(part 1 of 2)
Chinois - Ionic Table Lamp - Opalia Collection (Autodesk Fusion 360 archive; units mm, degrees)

design "Marble Base - Ionic Table Lamp - Ketra Ready - 120V - Opalia Collection" references "Ketra - A20 Tunable Lamp", "Facet Petite", "Arca Tall", "Chinois", "Arca Petite", "Trove - TL", "Marble Base - Ionic Table Lamp - Ketra Ready - 120V"
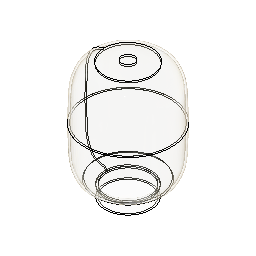
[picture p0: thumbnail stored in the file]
component_insert "Component Insert2"
component_insert "Component Insert3"
component_insert "Component Insert4"
component_insert "Component Insert5"
position "Position1"
component_insert "Component Insert6"
component_insert "Component Insert7"
component_insert "Component Insert8"

design "Arca Petite"
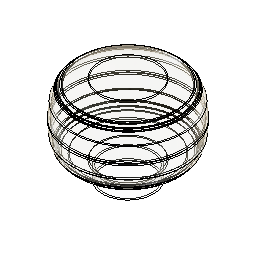
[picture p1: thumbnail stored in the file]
sketch "Sketch1" plane through (0, 0, 0) normal (0, 1, 0) x axis (1, 0, 0)
  line L1 (0, 101.6) -> (0, -101.6)
  line L2 (127, 0) -> (-127, 0)
  line L3 (63.5, 101.6) -> (-63.5, 101.6)
  perpendicular L1 L2
  parallel L2 L3
sketch "Sketch2" plane through (0, 0, 0) normal (0, 1, 0) x axis (1, 0, 0)
  line L1 (0, 101.6) -> (0, -101.6)
  line L2 (0, -76.2) -> (0, 101.6)
  line L3 (127, 0) -> (-127, 0)
  line L4 (114.3, 0) -> (-114.3, 0)
  line L5 (50.8, 101.6) -> (50.8, 63.5)
  line L6 (-50.8, 101.6) -> (50.8, 101.6)
  line L7 (-50.8, 63.5) -> (-50.8, 101.6)
  line L8 (63.5, 101.6) -> (-63.5, 101.6)
  line L9 (114.3, -76.2) -> (114.3, 63.5)
  line L10 (-114.3, -76.2) -> (114.3, -76.2)
  line L11 (-114.3, 63.5) -> (-114.3, -76.2)
  line L12 (-50.8, 63.5) -> (-114.3, 63.5)
  line L13 (114.3, 63.5) -> (50.8, 63.5)
  point P2 (0, 101.6)
  point P5 (0, 101.6)
  point P6 (0, -76.2)
  point P9 (-114.3, 0)
  point P10 (114.3, 0)
  point P11 (50.8, 101.6)
  point P19 (50.8, 63.5)
  coincident P2 P5
  coincident L1 P6
  coincident L3 P9
  coincident L3 P10
  vertical L5
  horizontal L6
  vertical L7
  coincident P11 L8
  horizontal L12
  vertical L9
  horizontal L10
  vertical L11
  coincident P19 L12
  collinear L12 L13
derived_base_feature "Derived Base Feature"
revolve "Revolve1" sketch "Sketch4" AlongAngle 360 bodies "Arca Petite"
shell "Shell1" innerThickness 3.81
component_from_bodies "Body->Comp"
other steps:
base_feature "Base Feature" bodies "Arca Petite"
create_component "CreateComponent1"
remove_body "RemoveBody1"
named bodies: "Arca Petite"

design "Neoprene Pad"
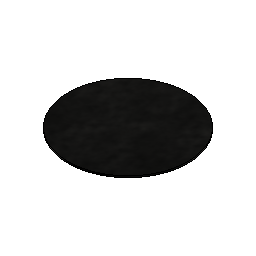
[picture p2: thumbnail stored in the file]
sketch "Sketch1" plane through (0, 0, 0) normal (0, 0, 1) x axis (1, 0, 0)
  circle C1 centre (0, 0) radius 57.15
  point P1 (0, 0)
  point P2 (0, 0)
  coincident P1 P2
extrude "Extrude1" new body sketch "Sketch1" along normal blind 1.5875 bodies "Neoprene Pad"
component_from_bodies "Body->Comp"
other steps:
base_feature "Base Feature" bodies "Neoprene Pad"
create_component "CreateComponent1"
remove_body "RemoveBody1"
named bodies: "Neoprene Pad"

design "T9 - Bulb"
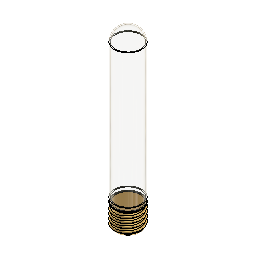
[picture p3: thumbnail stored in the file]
sketch "Sketch1" plane through (0, 0, 0) normal (0, 1, 0) x axis (1, 0, 0)
  line L1 (0, -166.37) -> (0, 0)
  line L2 (13.97, -13.97) -> (13.97, -152.4)
  line L3 (-13.97, -152.4) -> (-13.97, -13.97)
  line L4 (0, 0) -> (0, -166.37)
  line L5 (12.97, -13.97) -> (12.97, -152.4)
  line L6 (-12.97, -152.4) -> (-12.97, -13.97)
  line L7 (-12.3978, -10.16) -> (-13.4404, -10.16)
  line L8 (13.4404, -10.16) -> (12.3978, -10.16)
  arc A1 centre (0, -152.4) radius 13.97 clockwise from (13.97, -152.4) to (-13.97, -152.4)
  arc A2 centre (0, -152.4) radius 12.97 clockwise from (12.97, -152.4) to (-12.97, -152.4)
  arc A3 centre (0, -13.97) radius 13.97 clockwise from (13.4404, -10.16) to (13.97, -13.97)
  arc A4 centre (0, -13.97) radius 13.97 clockwise from (-13.97, -13.97) to (-13.4404, -10.16)
  arc A5 centre (0, -13.97) radius 12.97 clockwise from (12.3978, -10.16) to (12.97, -13.97)
  arc A6 centre (0, -13.97) radius 12.97 clockwise from (-12.97, -13.97) to (-12.3978, -10.16)
  point P1 (0, 0)
  point P2 (0, 0)
  point P3 (0, -166.37)
  point P10 (0, 0)
  point P17 (13.4404, -10.16)
  point P19 (12.3978, -10.16)
  point P4 (13.97, -152.4)
  point P5 (13.97, -13.97)
  coincident P1 P2
  vertical L1
  tangent L2 A3
  tangent L3 A3
  parallel L2 L3
  tangent L3 A1
  tangent L2 A1
  midpoint P3 A1
  coincident P1 P10
  perpendicular L1 L7
  coincident P17 L7
  concentric A3 A4
  coincident P10 A3
  concentric A1 A2
  tangent L5 A2
  tangent L5 A5
  tangent L6 A5
  tangent L6 A2
  coincident P19 L7
  concentric A5 A6
  collinear L7 L8
  dimension "d6" distance L2 L3 = 27.94
  dimension "d7" distance P4 P5 = 138.43
revolve "Revolve1" sketch "Sketch1" AlongAngle 360 bodies "T9"
derived_base_feature "Derived Base Feature" bodies "E26 Base"
align "Align1"
move "Move1"
component_from_bodies "Body->Comp1"
component_from_bodies "Body->Comp2"
copy_paste "CutPaste1"
copy_paste "CutPaste2"
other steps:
base_feature "Base Feature1" bodies "T9"
base_feature "Base Feature1" bodies "E26 Base"
create_component "CreateComponent1"
create_component "CreateComponent2"
remove_body "RemoveBody1"
create_component "CreateComponent3"
remove_body "RemoveBody2"
remove_instance "RemoveInstance1"
remove_instance "RemoveInstance2"
named bodies: "T9", "E26 Base"

design "Marble Base - Silicone Gasket"
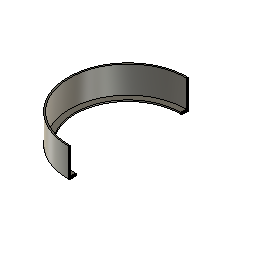
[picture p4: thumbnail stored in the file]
sketch "Sketch1" plane through (0, 0, 0) normal (0, 0, 1) x axis (1, 0, 0)
  circle C1 centre (0, 0) radius 53.34
  point P1 (0, 0)
  point P2 (0, 0)
  coincident P1 P2
extrude "Extrude1" new body sketch "Sketch1" along normal blind 25.4 bodies "Silicone Gasket"
shell "Shell1" innerThickness 1.27
sketch "Sketch2" plane through (0, 0, 1.27) normal (0, 0, 1) x axis (-1, 0, 0)
  circle C1 centre (0, 0) radius 52.07
  circle C2 centre (0, 0) radius 46.99
  concentric C1 C2
extrude "Extrude2" cut sketch "Sketch2" profile of C2 against normal blind 12.7
component_from_bodies "Body->Comp"
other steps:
base_feature "Base Feature" bodies "Silicone Gasket"
create_component "CreateComponent1"
remove_body "RemoveBody1"
named bodies: "Silicone Gasket"

design "2-Pole Plug End"
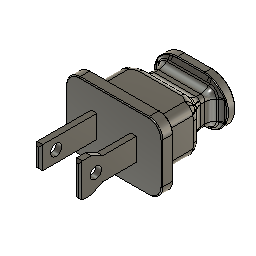
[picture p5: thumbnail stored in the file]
sketch "Sketch1" plane through (0, 0, 0) normal (0, 1, 0) x axis (1, 0, 0)
  line L1 (9.6837, 9.525) -> (-9.6837, 9.525)
  line L2 (13.4938, -5.715) -> (13.4938, 5.715)
  line L3 (-9.6837, -9.525) -> (9.6837, -9.525)
  line L4 (-13.4937, 5.715) -> (-13.4937, -5.715)
  line L5 (13.4938, -9.525) -> (-13.4937, 9.525)
  line L6 (-13.4937, -9.525) -> (13.4938, 9.525)
  arc A1 centre (-9.6837, -5.715) radius 3.81 clockwise from (-9.6837, -9.525) to (-13.4937, -5.715)
  arc A2 centre (9.6837, -5.715) radius 3.81 clockwise from (13.4938, -5.715) to (9.6837, -9.525)
  arc A3 centre (9.6837, 5.715) radius 3.81 clockwise from (9.6837, 9.525) to (13.4938, 5.715)
  arc A4 centre (-9.6837, 5.715) radius 3.81 clockwise from (-13.4937, 5.715) to (-9.6837, 9.525)
  point P6 (0, 0)
  point P1 (0, 0)
  point P5 (-13.4937, -9.525)
  point P4 (13.4938, -9.525)
  point P3 (13.4938, 9.525)
  point P2 (-13.4937, 9.525)
  horizontal L1
  perpendicular L1 L2
  parallel L1 L3
  parallel L2 L4
  coincident L5 P6
  coincident L6 P6
  coincident P1 P6
  coincident P5 L4
  coincident P5 L3
  tangent L4 A1
  tangent L3 A1
  coincident P4 L3
  coincident P4 L2
  tangent L3 A2
  tangent L2 A2
  equal A1 A2
  coincident P3 L2
  coincident P3 L1
  tangent L2 A3
  tangent L1 A3
  equal A1 A3
  coincident P2 L1
  coincident P2 L4
  tangent L1 A4
  tangent L4 A4
  equal A1 A4
  dimension "d1" distance P4 P5 = 26.9875
  dimension "d2" distance P2 P5 = 19.05
  dimension "d3" radius A1 = 3.81
extrude "Extrude1" new body sketch "Sketch1" profile of L1 L2 L3 L4 A1 A2 A3 A4 along normal blind 3.175
sketch "Sketch2" plane through (0, 3.175, 0) normal (0, 1, 0) x axis (-1, 0, 0)
  line L1 (9.6837, -9.525) -> (-9.6837, -9.525)
  line L2 (13.4937, 5.715) -> (13.4937, -5.715)
  line L3 (-9.6837, 9.525) -> (9.6837, 9.525)
  line L4 (-13.4938, -5.715) -> (-13.4938, 5.715)
  line L5 (10.16, -6.35) -> (-10.16, -6.35)
  line L6 (10.16, 6.35) -> (10.16, -6.35)
  line L7 (-10.16, 6.35) -> (10.16, 6.35)
  line L8 (-10.16, -6.35) -> (-10.16, 6.35)
  line L9 (10.16, 6.35) -> (-10.16, -6.35)
  line L10 (-10.16, 6.35) -> (10.16, -6.35)
  arc A1 centre (-9.6837, -5.715) radius 3.81 clockwise from (-9.6837, -9.525) to (-13.4938, -5.715)
  arc A2 centre (9.6837, -5.715) radius 3.81 clockwise from (13.4937, -5.715) to (9.6837, -9.525)
  arc A3 centre (9.6837, 5.715) radius 3.81 clockwise from (9.6837, 9.525) to (13.4937, 5.715)
  arc A4 centre (-9.6837, 5.715) radius 3.81 clockwise from (-13.4938, 5.715) to (-9.6837, 9.525)
  point P18 (0, 0)
  point P1 (0, 0)
  horizontal L5
  perpendicular L5 L6
  parallel L5 L7
  parallel L6 L8
  coincident L9 P18
  coincident L10 P18
  coincident P1 P18
extrude "Extrude2" add sketch "Sketch2" profile of L5 L6 L7 L8 along normal blind 9.525
sketch "Sketch3" plane through (0, 12.7, 0) normal (0, 1, 0) x axis (-1, 0, 0)
  line L1 (-10.16, -6.35) -> (-10.16, 6.35)
  line L2 (10.16, -6.35) -> (-10.16, -6.35)
  line L3 (10.16, 6.35) -> (10.16, -6.35)
  line L4 (-10.16, 6.35) -> (10.16, 6.35)
  line L5 (-7.1437, 3.9688) -> (7.1437, 3.9688)
  line L6 (-7.1437, -3.9688) -> (-7.1437, 3.9688)
  line L7 (7.1437, -3.9688) -> (-7.1437, -3.9688)
  line L8 (7.1437, 3.9688) -> (7.1437, -3.9688)
  line L9 (-7.1437, -3.9688) -> (7.1437, 3.9688)
  line L10 (7.1437, -3.9688) -> (-7.1437, 3.9688)
  point P10 (0, 0)
  point P1 (0, 0)
  point P8 (-7.1437, -3.9688)
  point P9 (7.1437, -3.9688)
  point P7 (-7.1437, 3.9688)
  horizontal L5
  perpendicular L5 L6
  parallel L5 L7
  parallel L6 L8
  coincident L9 P10
  coincident L10 P10
  coincident P1 P10
  dimension "d8" distance P8 P9 = 14.2875
  dimension "d9" distance P7 P8 = 7.9375
extrude "Extrude3" add sketch "Sketch3" profile of L5 L6 L7 L8 along normal blind 11.1125
fillet "Fillet1" radius 2.286 1.27 0.254
chamfer "Chamfer1" distance 3.429
fillet "Fillet2" radius 2.54 1.905
sketch "Sketch4" plane through (0, 23.8125, 0) normal (0, 1, 0) x axis (-1, 0, 0)
  line L1 (-7.1437, -2.6987) -> (-7.1437, 2.6987)
  line L2 (5.8737, -3.9688) -> (-5.8737, -3.9688)
  line L3 (7.1437, 2.6987) -> (7.1437, -2.6987)
  line L4 (-5.8737, 3.9688) -> (5.8737, 3.9688)
  line L5 (-3.81, 6.604) -> (3.81, 6.604)
  line L6 (3.81, -6.604) -> (-3.81, -6.604)
  line L7 (-10.414, 0) -> (10.414, 0)
  arc A1 centre (-5.8737, 2.6987) radius 1.27 clockwise from (-7.1437, 2.6987) to (-5.8737, 3.9688)
  arc A2 centre (-5.8737, -2.6987) radius 1.27 clockwise from (-5.8737, -3.9688) to (-7.1437, -2.6987)
  arc A3 centre (5.8737, -2.6987) radius 1.27 clockwise from (7.1437, -2.6987) to (5.8737, -3.9688)
  arc A4 centre (5.8737, 2.6987) radius 1.27 clockwise from (5.8737, 3.9688) to (7.1437, 2.6987)
  arc A5 centre (-3.81, 0) radius 6.604 clockwise from (-3.81, -6.604) to (-3.81, 6.604)
  arc A6 centre (3.81, 0) radius 6.604 clockwise from (3.81, 6.604) to (3.81, -6.604)
  point P20 (10.414, 0)
  point P21 (-10.414, 0)
  tangent L5 A5
  tangent A5 L6
  parallel L5 L6
  tangent L6 A6
  tangent L5 A6
  midpoint A6 P20
  midpoint A5 P21
  perpendicular L1 L7
extrude "Extrude4" add sketch "Sketch4" profile of A1 L1 A2 L2 A3 L3 A4 L4 L5 A5 L6 A6 against normal blind 2.286
chamfer "Chamfer2" distance 1.778
fillet "Fillet3" radius 1.778
fillet "Fillet4" radius 0.254
fillet "Fillet5" radius 0.254
fillet "Fillet6" radius 0.254
fillet "Fillet7" radius 3.175
sketch "Sketch5" plane through (0, 0, 0) normal (0, -1, 0) x axis (1, 0, 0)
  line L1 (-13.2397, -5.715) -> (-13.2397, 5.715)
  line L2 (9.6837, -9.271) -> (-9.6837, -9.271)
  line L3 (13.2397, 5.715) -> (13.2397, -5.715)
  line L4 (-9.6837, 9.271) -> (9.6837, 9.271)
  line L5 (-6.35, -3.175) -> (-6.35, 3.175)
  line L6 (6.35, 3.175) -> (-6.35, -3.175)
  line L7 (-6.35, 3.175) -> (6.35, -3.175)
  line L8 (-4.7625, 3.175) -> (-6.35, 3.175)
  line L9 (-4.7625, -3.175) -> (-4.7625, 3.175)
  line L10 (-6.35, -3.175) -> (-4.7625, -3.175)
  line L11 (-6.35, 3.175) -> (-6.35, -3.175)
  line L12 (0, -3.302) -> (0, 3.81)
  line L13 (4.7625, -3.175) -> (4.7625, 3.175)
  line L14 (4.7625, 3.175) -> (6.35, 3.175)
  line L15 (6.35, -3.175) -> (6.35, 3.175)
  line L16 (6.35, -3.175) -> (4.7625, -3.175)
  arc A1 centre (-9.6837, 5.715) radius 3.556 clockwise from (-13.2397, 5.715) to (-9.6837, 9.271)
  arc A2 centre (-9.6837, -5.715) radius 3.556 clockwise from (-9.6837, -9.271) to (-13.2397, -5.715)
  arc A3 centre (9.6837, -5.715) radius 3.556 clockwise from (13.2397, -5.715) to (9.6837, -9.271)
  arc A4 centre (9.6837, 5.715) radius 3.556 clockwise from (9.6837, 9.271) to (13.2397, 5.715)
  point P18 (0, 0)
  point P1 (0, 0)
  point P14 (-6.35, -3.175)
  point P27 (6.35, -3.175)
  point P17 (-6.35, 3.175)
  point P26 (6.35, 3.175)
  point P19 (-4.7625, 3.175)
  point P24 (4.7625, 3.175)
  point P20 (-4.7625, -3.175)
  point P25 (4.7625, -3.175)
  point P21 (-6.35, -3.175)
  point P28 (6.35, -3.175)
  point P15 (6.35, -3.175)
  point P16 (6.35, 3.175)
  coincident L6 P18
  coincident L7 P18
  coincident P1 P18
  horizontal L8
  vertical L9
  horizontal L10
  vertical L11
  vertical L12
  symmetric P14 L12 P27
  symmetric P17 L12 P26
  symmetric P19 L12 P24
  symmetric P20 L12 P25
  symmetric P21 L12 P28
  dimension "d36" distance P15 P16 = 6.35
  dimension "d37" distance P17 P19 = 1.5875
extrude "Extrude5" add sketch "Sketch5" profile of L5 L8 L9 L10 L11 L13 L14 L15 L16 along normal blind 15.875
sketch "Sketch7" plane through (0, 0, 3.175) normal (0, 0, 1) x axis (-1, 0, 0)
  line L1 (-4.7625, 0) -> (-6.35, 0)
  line L2 (-4.7625, 15.875) -> (-4.7625, 0)
  line L3 (-6.35, 15.875) -> (-4.7625, 15.875)
  line L4 (-6.35, 0) -> (-6.35, 15.875)
  line L5 (-4.7625, 15.875) -> (-6.35, 15.875)
  line L6 (-4.7625, 9.525) -> (-4.7625, 15.875)
  line L7 (-6.35, 9.525) -> (-4.7625, 9.525)
  line L8 (-6.35, 15.875) -> (-6.35, 9.525)
  point P5 (-6.35, 15.875)
  point P6 (-6.35, 15.875)
  point P9 (-6.35, 9.525)
  horizontal L5
  vertical L6
  horizontal L7
  vertical L8
  coincident P5 P6
  dimension "d45" distance P6 P9 = 6.35
extrude "Extrude7" add sketch "Sketch7" profile of L2 L3 L4 L5 L6 L7 L8 against normal blind 7.9375 and along normal blind 1.5875
chamfer "Chamfer3" distance 0.508
chamfer "Chamfer4" distance 0.635 distance 0.635
sketch "Sketch6" plane through (6.35, 0, 0) normal (1, 0, 0) x axis (0, 1, 0)
  line L1 (0, -3.175) -> (-9.525, -3.175)
  line L2 (0, 3.175) -> (0, -3.175)
  line L3 (-9.525, 3.175) -> (0, 3.175)
  line L4 (-15.367, -4.6355) -> (-15.367, 4.6355)
  line L5 (-11.43, 0) -> (-16.002, 0)
  line L6 (-9.525, -4.7625) -> (-15.24, -4.7625)
  line L7 (-9.525, -3.175) -> (-9.525, -4.7625)
  line L8 (-9.525, 4.7625) -> (-9.525, 3.175)
  line L9 (-15.24, 4.7625) -> (-9.525, 4.7625)
  line L10 (-15.24, -4.7625) -> (-15.367, -4.6355)
  line L11 (-15.367, 4.6355) -> (-15.24, 4.7625)
  circle C1 centre (-11.43, 0) radius 1.5875
  point P9 (-11.43, 0)
  point P10 (-11.43, 0)
  perpendicular L4 L5
  coincident P9 P10
  dimension "d42" diameter C1 = 3.175
extrude "Extrude6" cut sketch "Sketch6" profile of C1 against normal blind 20.32
chamfer "Chamfer5" distance 3.175 distance 1.5875 distance 3.175 distance 1.5875
component_from_bodies "Body->Comp"
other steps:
base_feature "Base Feature" bodies "2-Pole Plug End"
create_component "CreateComponent1"
remove_body "RemoveBody1"
named bodies: "2-Pole Plug End"

design "Facet Petite"
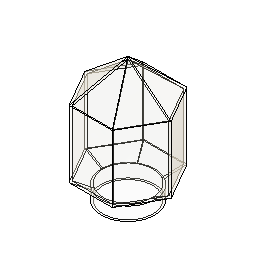
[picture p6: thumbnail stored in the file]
sketch "Sketch7" plane through (0, 0, 0) normal (1, 0, 0) x axis (0, 1, 0)
sketch "Sketch8" plane through (0, 0, 0) normal (0, 0, 1) x axis (1, 0, 0)
  circle C1 centre (0, 0) radius 50.8
  point P1 (0, 0)
  point P2 (0, 0)
  coincident P1 P2
  dimension "d17" diameter C1 = 101.6
extrude "Extrude5" new body sketch "Sketch8" along normal blind 25.4 and against normal blind 25.4
work_plane "WorkPlane1" AlongDistance 17.78
sketch "Sketch10" plane through (0, 0, 25.4) normal (0, 0, 1) x axis (-1, 0, 0)
  circle C1 centre (0, 0) radius 50.8
sketch "Sketch12" plane through (0, 0, 43.18) normal (0, 0, 1) x axis (1, 0, 0)
  line L1 (-82.1223, 0) -> (-41.0612, 71.12)
  line L2 (-41.0612, -71.12) -> (-82.1223, 0)
  line L3 (41.0612, -71.12) -> (-41.0612, -71.12)
  line L4 (82.1223, 0) -> (41.0612, -71.12)
  line L5 (41.0612, 71.12) -> (82.1223, 0)
  line L6 (-41.0612, 71.12) -> (41.0612, 71.12)
  point P1 (0, 0)
  point P8 (0, 0)
  coincident P1 P8
  dimension "d22" distance P8 L6 = 71.12
sketch "Sketch15" plane through (0, 0, 0) normal (0, 1, 0) x axis (1, 0, 0)
  line L1 (53.7365, -21.6801) -> (82.1223, -43.18)
  line L2 (-50.8, -25.4) -> (-82.1223, -43.18)
  point P2 (82.1223, -43.18)
  point P3 (82.1223, -43.18)
  point P5 (-82.1223, -43.18)
  point P7 (-82.1223, -43.18)
  point P6 (-50.8, -25.4)
  point P8 (-50.8, -25.4)
  coincident P2 P3
  coincident P5 P7
  coincident P6 P8
sketch "Sketch17" plane through (0, 0, 25.4) normal (0, 0, 1) x axis (-1, 0, 0)
  line L1 (51.3255, 0) -> (0, 0)
  line L2 (73.3235, 0) -> (0, 0)
  line L3 (-41.0612, -71.12) -> (-25.4, -43.9941)
  line L4 (-36.6617, -63.5) -> (-25.4, -43.9941)
  line L5 (78.4305, 0) -> (0, 0)
  line L6 (41.0612, -71.12) -> (25.4, -43.9941)
  line L7 (25.4, 43.9941) -> (41.0612, 71.12)
  line L8 (73.3235, 0) -> (0, 0)
  line L9 (-25.4, 43.9941) -> (-41.0612, 71.12)
  line L10 (0, 0) -> (0, 0)
  circle C1 centre (0, 0) radius 50.8
  point P1 (0, 0)
  point P4 (0, 0)
  point P2 (-41.0612, -71.12)
  point P6 (-41.0612, -71.12)
  point P3 (0, 0)
  point P7 (0, 0)
  point P9 (-25.4, -43.9941)
  point P12 (41.0612, -71.12)
  point P13 (41.0612, -71.12)
  point P15 (25.4, -43.9941)
  point P16 (41.0612, 71.12)
  point P17 (41.0612, 71.12)
  point P18 (25.4, 43.9941)
  point P19 (-41.0612, 71.12)
  point P20 (-41.0612, 71.12)
  point P21 (0, 0)
  point P23 (-25.4, 43.9941)
  point P25 (0, 0)
  point P24 (0, 0)
  point P26 (0, 0)
  horizontal L1
  coincident P1 P4
  coincident P2 P6
  horizontal L2
  coincident P3 P7
  coincident C1 P9
  coincident P12 P13
  horizontal L5
  coincident C1 P15
  coincident P16 P17
  coincident C1 P18
  coincident P19 P20
  horizontal L8
  coincident P1 P21
  coincident C1 P23
  coincident P1 P25
  coincident P24 P26
extrude "Extrude6" new body sketch "Sketch12" along normal blind 127
work_plane "WorkPlane2" AlongDistance 66.04
sketch "Sketch18" plane through (0, 0, 236.22) normal (0, 0, 1) x axis (1, 0, 0)
  line L1 (41.0612, -71.12) -> (0, 0)
  line L2 (82.1223, 0) -> (0, 0)
  line L3 (41.0612, 71.12) -> (0, 0)
  line L4 (-41.0612, 71.12) -> (0, 0)
  line L5 (-82.1223, 0) -> (0, 0)
  line L6 (-41.0612, -71.12) -> (0, 0)
  point P1 (0, 0)
  point P3 (0, 0)
  point P2 (41.0612, -71.12)
  point P4 (41.0612, -71.12)
  point P6 (0, 0)
  point P5 (82.1223, 0)
  point P7 (82.1223, 0)
  point P9 (0, 0)
  point P8 (41.0612, 71.12)
  point P10 (41.0612, 71.12)
  point P12 (0, 0)
  point P11 (-41.0612, 71.12)
  point P13 (-41.0612, 71.12)
  point P15 (0, 0)
  point P14 (-82.1223, 0)
  point P16 (-82.1223, 0)
  point P18 (0, 0)
  point P17 (-41.0612, -71.12)
  point P19 (-41.0612, -71.12)
  coincident P1 P3
  coincident P2 P4
  coincident P1 P6
  coincident P5 P7
  coincident P1 P9
  coincident P8 P10
  coincident P1 P12
  coincident P11 P13
  coincident P1 P15
  coincident P14 P16
  coincident P1 P18
  coincident P17 P19
loft "Loft1"
loft "Loft2" sketch "Sketch17"
component_from_bodies "Body->Comp"
extrude "Extrude1" cut of existing geometry blind -25.4
shell "Shell2" innerThickness 3.81
fillet "Fillet1" radius 7.62
fillet "Fillet2" radius 6.35
fillet "Fillet3" radius 6.35
fillet "Fillet4" radius 6.35
fillet "Fillet5" radius 6.35
fillet "Fillet6" radius 6.35
fillet "Fillet7" radius 3.81
fillet "Fillet8" radius 6.35
fillet "Fillet9" radius 6.35
fillet "Fillet10" radius 6.35
fillet "Fillet11" radius 6.35
fillet "Fillet12" radius 6.35
fillet "Fillet13" radius 2.286
shell "Shell1" innerThickness 2.54
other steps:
base_feature "Base Feature"
create_component "CreateComponent3"
remove_body "RemoveBody2"

design "Chinois"
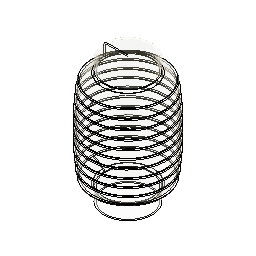
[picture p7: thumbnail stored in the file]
named bodies: "Chinois"

design "Marble Base - Plastic Insert"
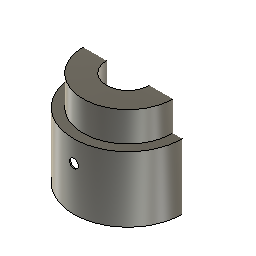
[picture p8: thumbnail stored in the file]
sketch "Sketch1" plane through (0, 0, 0) normal (0, 0, 1) x axis (1, 0, 0)
  circle C1 centre (0, 0) radius 50.038
  point P1 (0, 0)
  point P2 (0, 0)
  coincident P1 P2
  dimension "d1" diameter C1 = 100.076
extrude "Extrude1" new body sketch "Sketch1" along normal blind 72.898 bodies "Plastic Insert"
shell "Shell1" innerThickness 1.016
work_plane "WorkPlane1" AlongDistance 18.034
sketch "Sketch2" plane through (0, 0, 90.932) normal (0, 0, 1) x axis (1, 0, 0)
  circle C1 centre (0, 0) radius 20.701
  point P1 (0, 0)
  point P2 (0, 0)
  coincident P1 P2
  dimension "d6" diameter C1 = 41.402
extrude "Extrude2" add sketch "Sketch2" against normal blind 65.024
shell "Shell2" innerThickness 1.016
sketch "Sketch3" plane through (0, 0, 0) normal (0, 1, 0) x axis (1, 0, 0)
  line L1 (5.08, -20.32) -> (-5.08, -20.32)
  line L2 (5.08, 20.32) -> (5.08, -20.32)
  line L3 (-5.08, 20.32) -> (5.08, 20.32)
  line L4 (-5.08, -20.32) -> (-5.08, 20.32)
  line L5 (5.08, 20.32) -> (-5.08, -20.32)
  line L6 (-5.08, 20.32) -> (5.08, -20.32)
  point P6 (0, 0)
  point P1 (0, 0)
  horizontal L1
  perpendicular L1 L2
  parallel L1 L3
  parallel L2 L4
  coincident L5 P6
  coincident L6 P6
  coincident P1 P6
extrude "Extrude3" cut sketch "Sketch3" profile of L1 L2 L3 L4 along normal blind 91.44
sketch "Sketch4" plane through (0, 0, 0) normal (0, 1, 0) x axis (1, 0, 0)
  line L1 (0, -40.64) -> (0, 0)
  circle C1 centre (0, -40.64) radius 4.064
  point P1 (0, 0)
  point P2 (0, 0)
  point P3 (0, -40.64)
  point P4 (0, -40.64)
  coincident P1 P2
  vertical L1
  coincident P3 P4
  dimension "d12" diameter C1 = 8.128
work_plane "WorkPlane2" AlongDistance -91.44
sketch "Sketch5" plane through (0, -91.44, 0) normal (0, 1, 0) x axis (1, 0, 0)
  circle C1 centre (0, -40.64) radius 4.064
extrude "Extrude4" cut sketch "Sketch5" along normal blind 63.5
sketch "Sketch6" plane through (0, 0, 26.924) normal (0, 0, 1) x axis (-1, 0, 0)
  circle C1 centre (0, 0) radius 19.685
  circle C2 centre (0, 0) radius 5.461
  concentric C1 C2
  dimension "d16" diameter C2 = 10.922
extrude "Extrude5" cut sketch "Sketch6" profile of C2 against normal blind 15.24
sketch "Sketch7" plane through (0, 0, 72.898) normal (0, 0, 1) x axis (-1, 0, 0)
  circle C1 centre (0, 0) radius 20.701
  circle C2 centre (0, 0) radius 50.038
  circle C3 centre (0, 0) radius 20.701
  circle C4 centre (0, 0) radius 45.72
  point P1 (0, 0)
  point P3 (0, 0)
  point P4 (0, 0)
  coincident P1 P3
  coincident P1 P4
extrude "Extrude6" add sketch "Sketch7" profile of C1 C3 C4 along normal blind 18.034
sketch "Sketch8" plane through (0, 0, 71.882) normal (0, 0, -1) x axis (1, 0, 0)
  circle C1 centre (0, 0) radius 20.701
  circle C2 centre (0, 0) radius 49.022
  circle C3 centre (0, 0) radius 20.701
  circle C4 centre (0, 0) radius 44.704
  point P1 (0, 0)
  point P3 (0, 0)
  point P4 (0, 0)
  coincident P1 P3
  coincident P1 P4
  dimension "d21" diameter C4 = 89.408
extrude "Extrude7" cut sketch "Sketch8" profile of C1 C3 C4 against normal blind 17.78
extrude "Extrude8" add of existing geometry blind 9.398
extrude "Extrude9" cut of existing geometry blind -9.398
component_from_bodies "Body->Comp"
offset_faces "OffsetFaces1" distance 4.445
offset_faces "OffsetFaces2" distance -4.445
offset_faces "OffsetFaces3" distance 3.175
offset_faces "OffsetFaces4" distance 3.175
offset_faces "OffsetFaces5" distance 3.175
offset_faces "OffsetFaces6" distance -3.175
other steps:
base_feature "Base Feature" bodies "Plastic Insert"
create_component "CreateComponent1"
remove_body "RemoveBody1"
named bodies: "Plastic Insert"

design "Arca Tall"
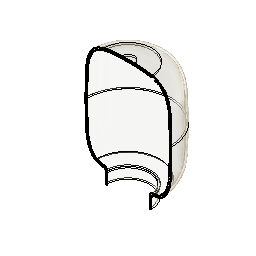
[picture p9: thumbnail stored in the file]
derived_base_feature "Derived Base Feature" bodies "Balon"
work_plane "WorkPlane1" AlongDistance 0
sketch "Sketch1" plane through (0, 0, 0) normal (0, 1, 0) x axis (1, 0, 0)
  line L1 (0, 317.5) -> (0, 2.9083)
  curve K1 (-82.9821, 124.2212) -> (-50.8, 237.8015)
  curve K2 (-51.0925, 237.681) -> (-50.8, 237.8015)
  curve K3 (-51.3855, 237.5558) -> (-51.0925, 237.681)
  curve K4 (-54.7608, 236.0513) -> (-51.3855, 237.5558)
  curve K5 (-57.9615, 234.05) -> (-54.7608, 236.0513)
  curve K6 (-67.2727, 226.749) -> (-57.9615, 234.05)
  curve K7 (-69.0552, 224.2615) -> (-67.2727, 226.749)
  curve K8 (-72.1872, 218.7832) -> (-69.0552, 224.2615)
  curve K9 (-74.1213, 215.1556) -> (-72.1872, 218.7832)
  curve K10 (-78.3031, 204.3965) -> (-74.1213, 215.1556)
  curve K11 (-79.7275, 197.3397) -> (-78.3031, 204.3965)
  curve K12 (-81.3333, 185.4664) -> (-79.7275, 197.3397)
  curve K13 (-81.6254, 178.4008) -> (-81.3333, 185.4664)
  curve K14 (-82.49, 152.2133) -> (-81.6254, 178.4008)
  curve K15 (-82.9821, 136.067) -> (-82.49, 152.2133)
  curve K16 (-82.9821, 124.2212) -> (-82.9821, 136.067)
  curve K17 (50.8, 237.7999) -> (82.9821, 124.2212)
  curve K18 (82.9821, 140.3031) -> (82.9821, 124.2212)
  curve K19 (81.9353, 169.4257) -> (82.9821, 140.3031)
  curve K20 (81.3621, 183.6489) -> (81.9353, 169.4257)
  curve K21 (80.9478, 189.8724) -> (81.3621, 183.6489)
  curve K22 (77.8147, 206.9858) -> (80.9478, 189.8724)
  curve K23 (74.9652, 213.2153) -> (77.8147, 206.9858)
  curve K24 (69.4688, 224.1531) -> (74.9652, 213.2153)
  curve K25 (67.2512, 226.458) -> (69.4688, 224.1531)
  curve K26 (61.5696, 231.3138) -> (67.2512, 226.458)
  curve K27 (57.377, 234.6711) -> (61.5696, 231.3138)
  curve K28 (52.0556, 237.2628) -> (57.377, 234.6711)
  curve K29 (51.4313, 237.5413) -> (52.0556, 237.2628)
  curve K30 (50.8, 237.7999) -> (51.4313, 237.5413)
  line L2 (-50.8, 317.5) -> (-50.8, 237.8015)
  line L3 (50.8, 317.5) -> (50.8, 237.7999)
  line L4 (-19.0713, 6.7501) -> (-19.0713, 6.7501)
  curve K31 (82.9821, 124.1958) -> (40.1509, 7.3012)
  curve K32 (41.8198, 7.6176) -> (40.1509, 7.3012)
  curve K33 (43.2113, 8.0663) -> (41.8198, 7.6176)
  curve K34 (47.0139, 9.2854) -> (43.2113, 8.0663)
  curve K35 (47.3314, 9.3805) -> (47.0139, 9.2854)
  curve K36 (50.1192, 10.3272) -> (47.3314, 9.3805)
  curve K37 (51.833, 11.0085) -> (50.1192, 10.3272)
  curve K38 (57.8313, 14.1895) -> (51.833, 11.0085)
  curve K39 (61.4491, 17.0488) -> (57.8313, 14.1895)
  curve K40 (66.8203, 21.5867) -> (61.4491, 17.0488)
  curve K41 (68.5372, 23.5528) -> (66.8203, 21.5867)
  curve K42 (71.2201, 27.8971) -> (68.5372, 23.5528)
  curve K43 (74.7424, 33.8984) -> (71.2201, 27.8971)
  curve K44 (78.2342, 44.8406) -> (74.7424, 33.8984)
  curve K45 (79.6792, 50.3463) -> (78.2342, 44.8406)
  curve K46 (81.3558, 63.5576) -> (79.6792, 50.3463)
  curve K47 (81.6386, 70.4415) -> (81.3558, 63.5576)
  curve K48 (82.4897, 96.2198) -> (81.6386, 70.4415)
  curve K49 (82.9814, 112.3523) -> (82.4897, 96.2198)
  curve K50 (82.9821, 124.1958) -> (82.9814, 112.3523)
  curve K51 (-40.1501, 7.301) -> (-82.9821, 124.1958)
  curve K52 (-82.9813, 110.5256) -> (-82.9821, 124.1958)
  curve K53 (-82.2545, 88.8594) -> (-82.9813, 110.5256)
  curve K54 (-81.6277, 70.519) -> (-82.2545, 88.8594)
  curve K55 (-81.3572, 64.3441) -> (-81.6277, 70.519)
  curve K56 (-79.4149, 46.8924) -> (-81.3572, 64.3441)
  curve K57 (-76.5204, 38.9768) -> (-79.4149, 46.8924)
  curve K58 (-73.5142, 32.2947) -> (-76.5204, 38.9768)
  curve K59 (-72.5556, 30.3818) -> (-73.5142, 32.2947)
  curve K60 (-69.7914, 25.3691) -> (-72.5556, 30.3818)
  curve K61 (-68.3824, 23.4028) -> (-69.7914, 25.3691)
  curve K62 (-64.5419, 19.5456) -> (-68.3824, 23.4028)
  curve K63 (-62.3002, 17.7646) -> (-64.5419, 19.5456)
  curve K64 (-53.6583, 11.1976) -> (-62.3002, 17.7646)
  curve K65 (-49.6968, 10.1396) -> (-53.6583, 11.1976)
  curve K66 (-43.4141, 8.1331) -> (-49.6968, 10.1396)
  curve K67 (-41.9704, 7.6516) -> (-43.4141, 8.1331)
  curve K68 (-40.1963, 7.3098) -> (-41.9704, 7.6516)
  curve K69 (-40.1732, 7.3054) -> (-40.1963, 7.3098)
  curve K70 (-40.1501, 7.301) -> (-40.1732, 7.3054)
  line L5 (-82.9821, 124.1958) -> (-82.9821, 124.2212)
  line L6 (82.9821, 124.2212) -> (82.9821, 124.1958)
  line L7 (0, 317.5) -> (-50.8, 317.5)
  line L8 (7.2015, 3.048) -> (0, 3.048)
  line L9 (0, 3.048) -> (-7.2015, 3.048)
  arc A1 centre (0, 188.595) radius 185.6867 clockwise from (-7.2015, 3.048) to (-40.1502, 7.301)
  arc A2 centre (0, 188.595) radius 185.6867 clockwise from (40.151, 7.3012) to (7.2015, 3.048)
  point P38 (-40.1502, 7.301)
  point P43 (40.1509, 7.3012)
  point P62 (-40.1501, 7.301)
  point P81 (40.151, 7.3012)
  point P84 (0, 3.048)
  vertical L1
  horizontal L4
  coincident P38 K51
  symmetric L1 A1 A2
  coincident A2 P43
  coincident A1 P62
  coincident K31 P81
  perpendicular L2 L7
  horizontal L8
  coincident L1 P84
  horizontal L9
revolve "Revolve1" sketch "Sketch1" AlongAngle 360
shell "Shell1" innerThickness 3.81
fillet "Fillet1" radius 6.35 bodies "Balon v3"
offset_faces "OffsetFaces1" distance -50.8
move "Move1"
move "Move2"
component_from_bodies "Body->Comp1"
component_from_bodies "Body->Comp2"
sketch "Sketch2" plane through (0, 0, 0) normal (0, 1, 0) x axis (1, 0, 0)
  line L1 (-85.5221, 124.2212) -> (-85.5221, 124.1961)
  curve K1 (-58.9057, 236.4383) -> (-50.8, 241.7989)
  curve K2 (-50.8, 241.554) -> (-50.8, 241.7989)
  curve K3 (-50.904, 240.933) -> (-50.8, 241.554)
  curve K4 (-51.2936, 240.2837) -> (-50.904, 240.933)
  curve K5 (-51.734, 239.7561) -> (-51.2936, 240.2837)
  curve K6 (-53.328, 238.5038) -> (-51.734, 239.7561)
  curve K7 (-54.0892, 238.1997) -> (-53.328, 238.5038)
  curve K8 (-58.9057, 236.4383) -> (-54.0892, 238.1997)
  curve K9 (-89.3309, 124.2212) -> (-58.9057, 236.4383)
  curve K10 (-62.6336, 234.9735) -> (-58.9057, 236.4383)
  curve K11 (-65.581, 233.1032) -> (-62.6336, 234.9735)
  curve K12 (-73.0224, 227.0019) -> (-65.581, 233.1032)
  curve K13 (-74.8981, 224.836) -> (-73.0224, 227.0019)
  curve K14 (-78.1104, 219.6097) -> (-74.8981, 224.836)
  curve K15 (-80.2663, 215.561) -> (-78.1104, 219.6097)
  curve K16 (-84.0943, 205.8277) -> (-80.2663, 215.561)
  curve K17 (-85.4655, 200.1154) -> (-84.0943, 205.8277)
  curve K18 (-87.4092, 188.5789) -> (-85.4655, 200.1154)
  curve K19 (-87.7349, 182.3889) -> (-87.4092, 188.5789)
  curve K20 (-88.4233, 165.9645) -> (-87.7349, 182.3889)
  curve K21 (-89.328, 138.6964) -> (-88.4233, 165.9645)
  curve K22 (-89.3309, 124.2212) -> (-89.328, 138.6964)
  line L2 (-89.3309, 124.1958) -> (-89.3309, 124.2212)
  curve K23 (-46.5001, 7.301) -> (-89.3309, 124.1958)
  curve K24 (-89.3314, 112.4293) -> (-89.3309, 124.1958)
  curve K25 (-88.8181, 95.3068) -> (-89.3314, 112.4293)
  curve K26 (-88.346, 81.2892) -> (-88.8181, 95.3068)
  curve K27 (-88.0298, 70.4902) -> (-88.346, 81.2892)
  curve K28 (-87.1514, 58.328) -> (-88.0298, 70.4902)
  curve K29 (-86.3326, 50.6119) -> (-87.1514, 58.328)
  curve K30 (-81.0932, 33.6688) -> (-86.3326, 50.6119)
  curve K31 (-77.3163, 27.4309) -> (-81.0932, 33.6688)
  curve K32 (-74.8955, 23.6666) -> (-77.3163, 27.4309)
  curve K33 (-73.5108, 22.0741) -> (-74.8955, 23.6666)
  curve K34 (-70.2346, 19.0457) -> (-73.5108, 22.0741)
  curve K35 (-64.8094, 14.3548) -> (-70.2346, 19.0457)
  curve K36 (-56.6696, 10.3041) -> (-64.8094, 14.3548)
  curve K37 (-54.0053, 9.483) -> (-56.6696, 10.3041)
  curve K38 (-49.1487, 7.9411) -> (-54.0053, 9.483)
  curve K39 (-48.3482, 7.6526) -> (-49.1487, 7.9411)
  curve K40 (-46.5001, 7.301) -> (-48.3482, 7.6526)
  line L3 (0, 266.7) -> (0, 0)
  line L4 (0, 3.048) -> (-7.7894, 3.048)
  line L5 (-50.8, 266.7) -> (-50.8, 241.7989)
  line L6 (0, 266.7) -> (-50.8, 266.7)
  arc A1 centre (-6.9779, 188.7329) radius 185.6867 clockwise from (-7.7894, 3.048) to (-46.5001, 7.301)
  point P1 (0, 0)
  point P44 (0, 0)
  point P46 (0, 3.048)
  point P5 (-50.8, 241.554)
  point P49 (0, 266.7)
  coincident P1 P44
  coincident L3 P46
  coincident P5 L5
  coincident L3 P49
revolve "Revolve2" sketch "Sketch2" AlongAngle 360 bodies "Balon v3"
shell "Shell2" innerThickness 3.81
component_from_bodies "Body->Comp3"
remove_instance "RemoveInstance1"
remove_instance "RemoveInstance2"
sketch "Sketch1" plane through (0, 0, 0) normal (0, 1, 0) x axis (1, 0, 0)
  line L1 (-6.35, 3.048) -> (-14.1394, 3.048)
  curve K1 (-52.8501, 7.301) -> (-95.6809, 124.1958)
  curve K2 (-95.6814, 112.4293) -> (-95.6809, 124.1958)
  curve K3 (-95.1681, 95.3068) -> (-95.6814, 112.4293)
  curve K4 (-94.696, 81.2892) -> (-95.1681, 95.3068)
  curve K5 (-94.3798, 70.4902) -> (-94.696, 81.2892)
  curve K6 (-93.5014, 58.328) -> (-94.3798, 70.4902)
  curve K7 (-92.6826, 50.6119) -> (-93.5014, 58.328)
  curve K8 (-87.4432, 33.6688) -> (-92.6826, 50.6119)
  curve K9 (-83.6663, 27.4309) -> (-87.4432, 33.6688)
  curve K10 (-81.2455, 23.6666) -> (-83.6663, 27.4309)
  curve K11 (-79.8608, 22.0741) -> (-81.2455, 23.6666)
  curve K12 (-76.5846, 19.0457) -> (-79.8608, 22.0741)
  curve K13 (-71.12, 13.97) -> (-76.5846, 19.0457)
  curve K14 (-62.23, 10.16) -> (-71.12, 13.97)
  curve K15 (-60.3553, 9.483) -> (-62.23, 10.16)
  curve K16 (-55.4987, 7.9411) -> (-60.3553, 9.483)
  curve K17 (-54.6982, 7.6526) -> (-55.4987, 7.9411)
  curve K18 (-52.8501, 7.301) -> (-54.6982, 7.6526)
  line L2 (-95.6809, 124.1958) -> (-95.6809, 124.2212)
  line L3 (0, 266.7) -> (0, 0)
  line L4 (0, 3.048) -> (-6.35, 3.048)
  line L5 (-95.6809, 124.2466) -> (-95.6809, 124.2212)
  line L6 (-50.8, 266.7) -> (-50.8, 241.7989)
  line L7 (0, 266.7) -> (-50.8, 266.7)
  curve K19 (-71.6837, 232.5587) -> (-50.8, 241.7989)
  curve K20 (-50.8, 237.8015) -> (-50.8, 241.7989)
  curve K21 (-53.6019, 236.5654) -> (-50.8, 237.8015)
  curve K22 (-59.7861, 236.0598) -> (-53.6019, 236.5654)
  curve K23 (-64.4375, 235.2772) -> (-59.7861, 236.0598)
  curve K24 (-69.8917, 233.4707) -> (-64.4375, 235.2772)
  curve K25 (-71.6837, 232.5587) -> (-69.8917, 233.4707)
  curve K26 (-71.6837, 232.5587) -> (-95.6809, 124.2466)
  curve K27 (-95.6814, 136.0132) -> (-95.6809, 124.2466)
  curve K28 (-95.1681, 153.1357) -> (-95.6814, 136.0132)
  curve K29 (-94.696, 167.1533) -> (-95.1681, 153.1357)
  curve K30 (-94.3798, 177.9523) -> (-94.696, 167.1533)
  curve K31 (-93.5014, 190.1145) -> (-94.3798, 177.9523)
  curve K32 (-92.6826, 197.8306) -> (-93.5014, 190.1145)
  curve K33 (-87.4432, 214.7737) -> (-92.6826, 197.8306)
  curve K34 (-83.6663, 221.0115) -> (-87.4432, 214.7737)
  curve K35 (-81.2455, 224.7759) -> (-83.6663, 221.0115)
  curve K36 (-79.8608, 226.3684) -> (-81.2455, 224.7759)
  curve K37 (-77.083, 228.9361) -> (-79.8608, 226.3684)
  curve K38 (-75.5537, 230.2778) -> (-77.083, 228.9361)
  curve K39 (-71.6837, 232.5587) -> (-75.5537, 230.2778)
  curve K40 (-50.8, 244.8458) -> (-50.8, 244.8469)
  curve K41 (-50.8, 244.8465) -> (-50.8, 244.8469)
  curve K42 (-50.8, 244.8462) -> (-50.8, 244.8465)
  curve K43 (-50.8, 244.8458) -> (-50.8, 244.8462)
  arc A1 centre (-13.3279, 188.7329) radius 185.6867 clockwise from (-14.1394, 3.048) to (-52.8501, 7.301)
  point P26 (0, 3.048)
  point P33 (-50.8, 237.8015)
  point P35 (-50.8, 237.8015)
  point P40 (-71.6837, 232.5587)
  point P53 (-50.8, 244.8458)
  coincident L3 P26
  perpendicular L3 L4
  coincident P33 P35
  coincident K19 P40
  coincident L6 P53
sketch "Sketch2" plane through (0, 0, 0) normal (0, 1, 0) x axis (1, 0, 0)
  line L1 (-95.6809, 124.1958) -> (-95.6809, 124.2212)
  line L2 (0, 266.7) -> (-50.8, 266.7)
  curve K1 (-58.9317, 239.3909) -> (-50.8, 244.8469)
  curve K2 (-50.8, 244.602) -> (-50.8, 244.8469)
  curve K3 (-50.904, 243.981) -> (-50.8, 244.602)
  curve K4 (-51.2936, 243.3317) -> (-50.904, 243.981)
  curve K5 (-51.734, 242.8041) -> (-51.2936, 243.3317)
  curve K6 (-53.328, 241.5518) -> (-51.734, 242.8041)
  curve K7 (-54.0892, 241.2477) -> (-53.328, 241.5518)
  curve K8 (-58.9317, 239.3909) -> (-54.0892, 241.2477)
  line L3 (-50.8, 266.7) -> (-50.8, 244.8458)
  curve K9 (-52.8501, 7.301) -> (-95.6809, 124.1958)
  curve K10 (-95.6814, 112.4293) -> (-95.6809, 124.1958)
  curve K11 (-95.1681, 95.3068) -> (-95.6814, 112.4293)
  curve K12 (-94.696, 81.2892) -> (-95.1681, 95.3068)
  curve K13 (-94.3798, 70.4902) -> (-94.696, 81.2892)
  curve K14 (-93.5014, 58.328) -> (-94.3798, 70.4902)
  curve K15 (-92.6826, 50.6119) -> (-93.5014, 58.328)
  curve K16 (-87.4432, 33.6688) -> (-92.6826, 50.6119)
  curve K17 (-83.6663, 27.4309) -> (-87.4432, 33.6688)
  curve K18 (-81.2455, 23.6666) -> (-83.6663, 27.4309)
  curve K19 (-79.8608, 22.0741) -> (-81.2455, 23.6666)
  curve K20 (-76.5846, 19.0457) -> (-79.8608, 22.0741)
  curve K21 (-73.7599, 16.6033) -> (-76.5846, 19.0457)
  curve K22 (-65.532, 11.7145) -> (-73.7599, 16.6033)
  curve K23 (-60.3553, 9.483) -> (-65.532, 11.7145)
  curve K24 (-55.4987, 7.9411) -> (-60.3553, 9.483)
  curve K25 (-54.6982, 7.6526) -> (-55.4987, 7.9411)
  curve K26 (-52.8501, 7.301) -> (-54.6982, 7.6526)
  line L4 (-95.6809, 124.2466) -> (-95.6809, 124.2212)
  line L5 (0, 3.048) -> (-6.35, 3.048)
  line L6 (-6.35, 3.048) -> (-14.1394, 3.048)
  curve K27 (-58.9317, 239.3909) -> (-95.6809, 124.2466)
  curve K28 (-95.6814, 136.0132) -> (-95.6809, 124.2466)
  curve K29 (-95.1681, 153.1357) -> (-95.6814, 136.0132)
  curve K30 (-94.696, 167.1533) -> (-95.1681, 153.1357)
  curve K31 (-94.3798, 177.9523) -> (-94.696, 167.1533)
  curve K32 (-93.5014, 190.1145) -> (-94.3798, 177.9523)
  curve K33 (-92.6826, 197.8306) -> (-93.5014, 190.1145)
  curve K34 (-87.4432, 214.7737) -> (-92.6826, 197.8306)
  curve K35 (-83.6663, 221.0115) -> (-87.4432, 214.7737)
  curve K36 (-81.2455, 224.7759) -> (-83.6663, 221.0115)
  curve K37 (-79.8608, 226.3684) -> (-81.2455, 224.7759)
  curve K38 (-76.5846, 229.3968) -> (-79.8608, 226.3684)
  curve K39 (-73.7599, 231.8391) -> (-76.5846, 229.3968)
  curve K40 (-65.833, 236.5491) -> (-73.7599, 231.8391)
  curve K41 (-61.4585, 238.4785) -> (-65.833, 236.5491)
  curve K42 (-58.9317, 239.3909) -> (-61.4585, 238.4785)
  line L7 (0, 3.048) -> (0, 266.7)
  arc A1 centre (-13.3279, 188.7329) radius 185.6867 clockwise from (-14.1394, 3.048) to (-52.8501, 7.301)
  point P52 (-50.8, 244.8458)
  coincident K1 P52
  perpendicular L5 L7
revolve "Revolve1" sketch "Sketch1" AlongAngle 360 bodies "Balon v3.3"
shell "Shell1" innerThickness 3.81
revolve "Revolve2" sketch "Sketch2" AlongAngle 360 bodies "Balon v3.2"
shell "Shell2" innerThickness 3.81
component_from_bodies "Body->Comp1"
component_from_bodies "Body->Comp2"
position "Position1"
remove_instance "RemoveInstance1" bodies "Balon v3"
remove_instance "RemoveInstance2"
move "Move1"
position "Position2" bodies "Balon v3"
sketch "Sketch3" plane through (0, 0, 0) normal (0, 1, 0) x axis (1, 0, 0)
  line L1 (0, 50.8) -> (0, -304.8)
  line L2 (127, 50.8) -> (127, -304.8)
  line L3 (-127, 50.8) -> (-127, -304.8)
  line L4 (139.7, 25.4) -> (-139.7, 25.4)
  line L5 (139.7, -292.1) -> (-139.7, -292.1)
  line L6 (95.25, 50.8) -> (95.25, -304.8)
  vertical L1
  dimension "d6" = 127
  dimension "d12" = -127
  dimension "d17" distance L4 L5 = 317.5
  dimension "d18" = 95.25
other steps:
base_feature "Base Feature1" bodies "Balon v3.3"
base_feature "Base Feature1" bodies "Balon v3.2"
base_feature "Base Feature1" bodies "Balon"
base_feature "Base Feature1" bodies "Balon v3"
base_feature "Base Feature1" bodies "Balon v2"
create_component "CreateComponent1"
remove_body "RemoveBody1"
create_component "CreateComponent2"
remove_body "RemoveBody2"
create_component "CreateComponent3"
remove_body "RemoveBody3" bodies "Balon v3"
create_component "CreateComponent1"
create_component "CreateComponent2"
remove_body "RemoveBody1" bodies "Balon v3"
create_component "CreateComponent3"
remove_body "RemoveBody2" bodies "Balon v3"
named bodies: "Balon", "Balon v2", "Balon v3", "Balon v3.3", "Balon v3.2"

design "Marble Base - Ionic Table Lamp - Ketra Ready - 120V" references "Marble Base - Ionic Table Lamp - 120V"
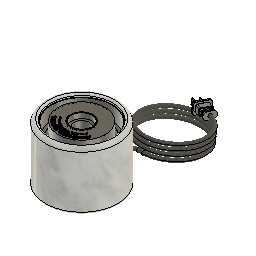
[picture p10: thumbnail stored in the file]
external_derived "ExternalDerived1" bodies "Coiled - SVT (Blk Fabric)", "Body1", "Marble Base", "Body2", "Silicone Gasket", "Plastic Insert"
derived_instance "DerivedInstance1"
derived_instance "DerivedInstance2"
derived_instance "DerivedInstance3"
derived_instance "DerivedInstance4"
derived_instance "DerivedInstance5"
derived_instance "DerivedInstance6"
derived_instance "DerivedInstance7"
derived_instance "DerivedInstance8"
derived_instance "DerivedInstance9"
derived_instance "DerivedInstance10"
derived_instance "DerivedInstance11"
derived_instance "DerivedInstance12"
offset_faces "OffsetFaces1" distance 3.81
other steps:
derived_base_feature "Derived Base Feature1" bodies "Rubber Grommet"
derived_base_feature "Derived Base Feature1" bodies "Neoprene Pad"
derived_base_feature "Derived Base Feature1" bodies "2-Pole Plug End"
derived_base_feature "Derived Base Feature1" bodies "Body1"
derived_base_feature "Derived Base Feature1" bodies "Body1", "Body2"
derived_base_feature "Derived Base Feature1" bodies "Body1"
derived_base_feature "Derived Base Feature1" bodies "Silicone Gasket"
derived_base_feature "Derived Base Feature1" bodies "Plastic Insert"
derived_base_feature "Derived Base Feature1" bodies "Body1"
derived_base_feature "Derived Base Feature1" bodies "Body1"
derived_base_feature "Derived Base Feature1" bodies "Coiled - SVT (Blk Fabric)"
derived_base_feature "Derived Base Feature1" bodies "Marble Base"
create_component "CreateComponent1"
create_component "CreateComponent2"
create_component "CreateComponent3"
create_component "CreateComponent4"
create_component "CreateComponent5"
create_component "CreateComponent6"
create_component "CreateComponent7"
create_component "CreateComponent8"
create_component "CreateComponent9"
create_component "CreateComponent10"
create_component "CreateComponent11"
create_component "CreateComponent12"
named bodies: "Coiled - SVT (Blk Fabric)", "Marble Base", "Body1", "Body2", "Plastic Insert", "Silicone Gasket", "Neoprene Pad", "2-Pole Plug End", "Rubber Grommet"

design "Rubber Grommet"
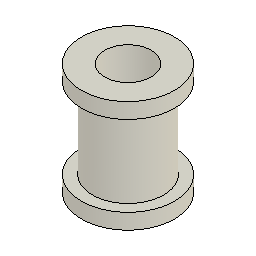
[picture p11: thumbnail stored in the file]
sketch "Sketch1" plane through (0, 0, 0) normal (0, 1, 0) x axis (1, 0, 0)
  line L1 (0, 3.048) -> (0, -12.7)
  line L2 (5.842, 0.508) -> (5.842, -12.7)
  line L3 (3.81, 3.048) -> (3.81, -15.24)
  line L4 (7.62, -12.7) -> (7.62, -15.24)
  line L5 (7.62, 3.048) -> (7.62, 0.508)
  line L6 (7.62, 0.508) -> (5.842, 0.508)
  line L7 (7.62, -12.7) -> (5.842, -12.7)
  line L8 (7.62, -15.24) -> (3.81, -15.24)
  line L9 (7.62, 3.048) -> (3.81, 3.048)
  vertical L1
  collinear L4 L5
revolve "Revolve1" sketch "Sketch1" AlongAngle 360 bodies "Rubber Grommet"
component_from_bodies "Body->Comp"
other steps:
base_feature "Base Feature" bodies "Rubber Grommet"
create_component "CreateComponent1"
remove_body "RemoveBody1"
named bodies: "Rubber Grommet"

design "Marble Base - Ionic Table Lamp - 120V" references "T9 - Bulb", "Arca Tall", "Facet Petite", "T9-5In", "Marble Base - Plastic Insert", "Rubber Grommet", "Neoprene Pad", "2-Pole Plug End", "Trove - TL", "Balon v2", "Chinois", "Marble Base - Silicone Gasket"
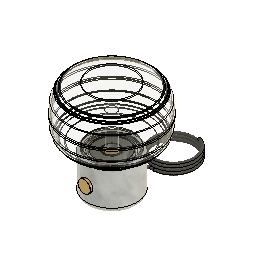
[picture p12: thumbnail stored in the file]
sketch "Sketch1" plane through (0, 0, 0) normal (0, 0, 1) x axis (1, 0, 0)
  circle C1 centre (0, 0) radius 63.5
  point P1 (0, 0)
  point P2 (0, 0)
  coincident P1 P2
extrude "Extrude1" new body sketch "Sketch1" along normal blind 101.6 bodies "Marble Base"
sketch "Sketch2" plane through (0, 0, 101.6) normal (0, 0, 1) x axis (-1, 0, 0)
  circle C1 centre (0, 0) radius 63.5
  circle C2 centre (0, 0) radius 53.975
  concentric C1 C2
  dimension "d3" diameter C2 = 107.95
extrude "Extrude2" cut sketch "Sketch2" profile of C2 against normal blind 34.925
sketch "Sketch3" plane through (0, 0, 66.675) normal (0, 0, 1) x axis (-1, 0, 0)
  circle C1 centre (0, 0) radius 53.975
  circle C2 centre (0, 0) radius 49.276
  point P1 (0, 0)
  point P3 (0, 0)
  coincident P1 P3
  dimension "d6" diameter C2 = 98.552
extrude "Extrude3" cut sketch "Sketch3" profile of C2 against normal blind 45.72
sketch "Sketch4" plane through (0, 0, 0) normal (0, 1, 0) x axis (1, 0, 0)
  circle C1 centre (0, -50.8) radius 3.81
  dimension "d9" diameter C1 = 7.62
extrude "Extrude4" cut sketch "Sketch4" against normal blind 127
sketch "Sketch5" plane through (0, 0, 0) normal (0, 1, 0) x axis (1, 0, 0)
  line L1 (0, -25.4) -> (0, 0)
  line L2 (0, -30.48) -> (0, -25.4)
  circle C1 centre (0, -30.48) radius 5.08
  point P1 (0, 0)
  point P2 (0, 0)
  point P4 (0, -30.48)
  point P5 (0, -30.48)
  coincident P1 P2
  vertical L1
  parallel L1 L2
  coincident P4 P5
  dimension "d12" diameter C1 = 10.16
extrude "Extrude5" cut sketch "Sketch5" profile of C1 along normal blind 114.3
fillet "Fillet1" radius 6.35 3.175 4.064
derived_base_feature "Derived Base Feature1" bodies "Rotary Switch"
derived_base_feature "Derived Base Feature1" bodies "Coiled - SVT (Blk Fabric)"
derived_base_feature "Derived Base Feature1" bodies "Glass Globe"
derived_base_feature "Derived Base Feature1" bodies "Metal Housing"
derived_base_feature "Derived Base Feature1" bodies "Metal Socket Cover"
derived_base_feature "Derived Base Feature1" bodies "Porcelain Socket"
derived_base_feature "Derived Base Feature1" bodies "Brass Dial - Dimmer Knob"
component_from_bodies "Body->Comp1"
offset_faces "OffsetFaces1" distance 12.7
offset_faces "OffsetFaces2" distance -12.7
derived_base_feature "Derived Base Feature1" bodies "Solitaire Petite"
move "Move1"
offset_faces "OffsetFaces1" distance 20.32
move "Move2"
extrude "Extrude6" add of existing geometry blind 25.4
offset_faces "OffsetFaces2" distance -3.81
fillet "Fillet2" radius 2.54
move "Move3"
derived_base_feature "Derived Base Feature2" bodies "Facet Petite"
move "Move4"
offset_faces "OffsetFaces1" distance 2.54
move "Move1"
derived_base_feature "Derived Base Feature1" bodies "Body1"
derived_base_feature "Derived Base Feature1" bodies "Body1"
derived_base_feature "Derived Base Feature1" bodies "Body1"
derived_base_feature "Derived Base Feature1" bodies "Body1"
derived_base_feature "Derived Base Feature1" bodies "Body1"
derived_base_feature "Derived Base Feature1" bodies "Body1", "Body2"
derived_base_feature "Derived Base Feature1" bodies "Body1"
position "Position1"
external_derived "ExternalDerived5" bodies "Plastic Insert"
derived_instance "DerivedInstance15"
offset_faces "OffsetFaces1" distance 3.81
offset_faces "OffsetFaces2" distance -1.0414
move "Move6"
external_derived "ExternalDerived6" sketch "Sketch3" bodies "Silicone Gasket"
derived_instance "DerivedInstance16"
offset_faces "OffsetFaces3" distance -10.795
move "Move1"
move_face "MoveFace1"
position "Position2"
position "Position3"
position "Position4"
position "Position5"
move "Move2"
position "Position6"
offset_faces "OffsetFaces2" distance -7.62
chamfer "Chamfer1" distance 0.381
remove_instance "RemoveInstance1"
remove_instance "RemoveInstance2"
remove_instance "RemoveInstance3"
remove_instance "RemoveInstance4"
move "Move1"
derived_base_feature "Derived Base Feature5" bodies "Oculo Petite"
align "Align1"
external_derived "ExternalDerived8"
derived_base_feature "Derived Base Feature7" bodies "Balon v2"
derived_base_feature "Derived Base Feature8" bodies "Balon v3"
align "Align3"
align "Align4"
external_derived "ExternalDerived10"
component_insert "Component Insert1"
position "Position7"
position "Position8"
derived_base_feature "Derived Base Feature11" bodies "Trove - TL"
move "Move10"
move "Move11"
remove_instance "RemoveInstance5"
split "Split1" bodies "Trove - TL (1)"
remove_body "RemoveBody2"
remove_body "RemoveBody3"
external_derived "ExternalDerived13" bodies "Trove - TL"
derived_instance "DerivedInstance20"
remove_body "RemoveBody4"
remove_body "RemoveBody5"
component_insert "Component Insert2"
component_insert "Component Insert3"
component_from_bodies "Body->Comp2"
remove_body "RemoveBody7"
move "Move12"
move "Move13"
sketch "Sketch6" plane through (0, 0, 97.917) normal (0, 0, 1) x axis (-1, 0, 0)
  circle C1 centre (0, 0) radius 41.275
  circle C2 centre (0, 0) radius 19.685
  arc A1 centre (0, 0) radius 29.3982 clockwise from (-27.6283, 10.0466) to (27.6283, 10.0466)
  arc A2 centre (0, 0) radius 26.2232 clockwise from (-24.6444, 8.9616) to (24.6444, 8.9616)
  arc A3 centre (0, 0) radius 32.5732 clockwise from (-30.6121, 11.1317) to (30.6121, 11.1317)
  arc A4 centre (0, 0) radius 35.7482 clockwise from (-33.596, 12.2167) to (33.596, 12.2167)
  point P1 (0, 0)
  point P3 (0, 0)
  coincident P1 P3
  dimension "d37" = -3.175
  dimension "d38" = 3.175
  dimension "d39" = 6.35
  dimension "d40" Text1-Height = 2.54
  dimension "d41" Text2-Height = 2.54
  dimension "d42" Text3-Height = 2.54
  dimension "d43" Text4-Height = 2.54
extrude "Extrude1" cut sketch "Sketch6" against normal blind 0.254
external_derived "ExternalDerived14" bodies "Rubber Grommet"
derived_instance "DerivedInstance19"
external_derived "ExternalDerived15" bodies "2-Pole Plug End"
derived_instance "DerivedInstance18"
external_derived "ExternalDerived16" bodies "Neoprene Pad"
derived_instance "DerivedInstance17"
position "Position9"
position "Position10"
position "Position11"
position "Position12"
external_derived "ExternalDerived17" bodies "Chinois"
derived_instance "DerivedInstance21"
position "Position13"
move "Move3"
remove_body "RemoveBody8"
component_insert "Component Insert4"
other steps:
derived_base_feature "Derived Base Feature1" bodies "Trove - TL"
derived_base_feature "Derived Base Feature1" bodies "Chinois"
derived_base_feature "Derived Base Feature1" bodies "Rubber Grommet"
derived_base_feature "Derived Base Feature1" bodies "2-Pole Plug End"
derived_base_feature "Derived Base Feature1" bodies "Neoprene Pad"
move "Move1"
base_feature "Base Feature1" bodies "Oculo Petite"
derived_base_feature "Derived Base Feature1" bodies "Plastic Insert"
derived_base_feature "Derived Base Feature1" bodies "Silicone Gasket"
base_feature "Base Feature1" bodies "Marble Base"
move "Move8"
derived_base_feature "Derived Base Feature"
create_component "CreateComponent1"
create_component "CreateComponent2"
create_component "CreateComponent3"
